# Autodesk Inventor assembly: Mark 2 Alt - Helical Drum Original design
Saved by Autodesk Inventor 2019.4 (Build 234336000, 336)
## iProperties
Created: 2020-06
Part Number: Mark 2 Alt - Helical Drum Original design
Document SubType Name: Assembly
Designer: Administrator
Title: Mark 2 Alt - Helical Drum Original design v20
Author: Administrator
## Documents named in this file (2)
- c:\worker\convert-fusion-r04\tmp\job-1\398\output\files\469cbb3d-9e2b-4d18-92c4-eb3d1ce46953\eba7637d-4a62-44a0-8f9d-8e1baf7ccb2b.iam
- c:\worker\convert-fusion-r04\tmp\job-1\398\output\files\469cbb3d-9e2b-4d18-92c4-eb3d1ce46953\Mark 2 Alt - Helical Drum Original design v20.ipt
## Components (1 placed, 1 different names)
1. Mark 2 Alt - Helical Drum Original design v20
